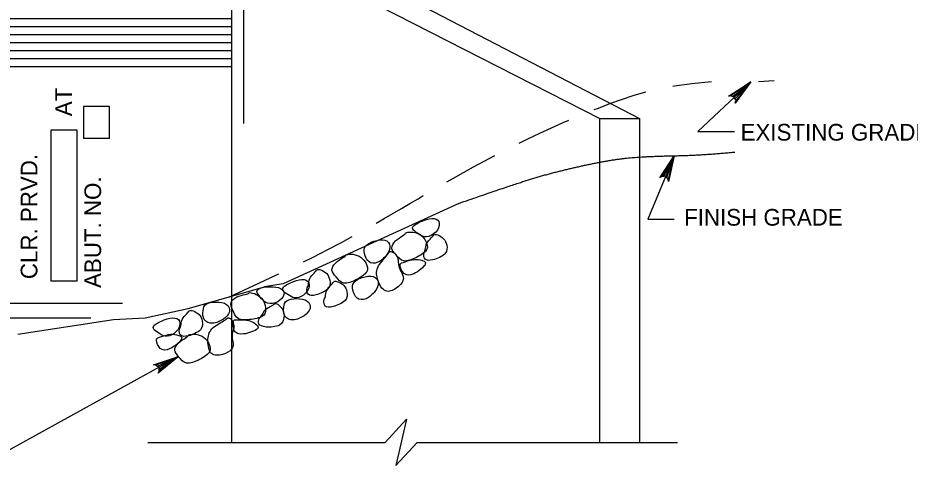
# Model space of a CAD drawing. Extents: x 638263 to 640391, y 293683 to 298655.
# Drawn here: x 638728.4 to 638888.9, y 297385.6 to 297468.7 of the extents above; entities that cross this region are included whole.
import ezdxf

# ---------------------------------------------------------------- set-up
doc = ezdxf.new("R2010")
doc.units = 0
for name, color, linetype in [('3', 7, 'Continuous'), ('4', 7, 'Continuous'), ('5', 7, 'Continuous'), ('8', 7, 'Continuous')]:
    doc.layers.add(name, color=color, linetype=linetype)

msp = doc.modelspace()

# ---------------------------------------------------------------- linework, layer by layer
at = {"layer": '3'}
for p, q in [((638766.86, 297484.49), (638833.06, 297450.61)), ((638775.07, 297484.49), (638840.19, 297450.61)), ((638766.86, 297480.17), (638766.86, 297418.67)), ((638574.49, 297459.98), (638766.86, 297459.98)), ((638860.22, 297457.21), (638850.73, 297448.28)), ((638833.06, 297450.61), (638840.19, 297450.61)), ((638833.06, 297442.76), (638833.06, 297450.61)), ((638840.19, 297450.61), (638840.19, 297443.67)), ((638850.73, 297448.28), (638857.33, 297448.28)), ((638833.06, 297392.39), (638833.06, 297442.76)), ((638840.19, 297443.67), (638840.19, 297392.39)), ((638846.45, 297443.93), (638841.69, 297432.53)), ((638807.71, 297435.38), (638776.12, 297420.89)), ((638841.69, 297432.53), (638846.46, 297432.53)), ((638776.12, 297420.89), (638772.8, 297420.39)), ((638766.86, 297418.67), (638766.86, 297392.39)), ((638580.85, 297414.78), (638741.58, 297414.78)), ((638794.47, 297392.39), (638798.31, 297396.56)), ((638798.31, 297396.56), (638796.38, 297388.22)), ((638751.78, 297392.39), (638794.47, 297392.39)), ((638796.38, 297388.22), (638800.23, 297392.39)), ((638800.23, 297392.39), (638847.06, 297392.39))]:
    msp.add_line(p, q, dxfattribs=at)
msp.add_lwpolyline([(638844.86, 297441.39), (638845.77, 297441.01), (638846.45, 297443.93)], close=True, dxfattribs=at)
for points, degree in [([(638807.71, 297435.38), (638815.49, 297438.06), (638822.64, 297440.39), (638829.78, 297442.14), (638836.53, 297443.45), (638842.88, 297443.88), (638851.42, 297444.03), (638857.38, 297444.61)], 2), ([(638799.58, 297430.54), (638799.82, 297430.29), (638800.68, 297429.73), (638801.79, 297429.09), (638803.77, 297430.03), (638804.53, 297431.96), (638803.44, 297432.86), (638801.42, 297432.42), (638799.24, 297431.28), (638799.34, 297430.8), (638799.58, 297430.54)], 3), ([(638798.16, 297429.99), (638798.11, 297429.9), (638797.78, 297429.62), (638796.19, 297428.7), (638795.39, 297427.27), (638796.4, 297426.22), (638797.6, 297424.59), (638800.18, 297425.59), (638802.4, 297427), (638801.85, 297428.6), (638801.06, 297429.73), (638799.46, 297430.33), (638798.11, 297430.13), (638798.22, 297430.07), (638798.16, 297429.99)], 3), ([(638790.94, 297427.65), (638790.66, 297427.28), (638790.69, 297426.44), (638791.32, 297424.61), (638793.16, 297424.48), (638794.91, 297426.1), (638795.61, 297427.73), (638794.64, 297429.07), (638792.37, 297428.67), (638791.22, 297428.02), (638790.94, 297427.65)], 3), ([(638801.7, 297427.05), (638801.63, 297426.74), (638801.33, 297426.38), (638801.48, 297425.16), (638802.82, 297424.99), (638805.72, 297426.24), (638805.62, 297427.99), (638805.11, 297429.09), (638803.85, 297429.8), (638803.2, 297429.83), (638802.9, 297429.22), (638801.73, 297428.18), (638801.76, 297427.35), (638801.7, 297427.05)], 3), ([(638795.26, 297426.68), (638795.12, 297426.59), (638795.01, 297426.13), (638792.74, 297423.82), (638792.99, 297421.61), (638794.39, 297419.03), (638796.59, 297420.04), (638798, 297421.54), (638797.53, 297422.92), (638796.78, 297423.93), (638796.93, 297425.77), (638795.84, 297426.67), (638795.4, 297426.77), (638795.26, 297426.68)], 3), ([(638787.39, 297426.01), (638787.33, 297425.92), (638787, 297425.64), (638785.41, 297424.72), (638784.62, 297423.29), (638785.62, 297422.24), (638786.83, 297420.61), (638789.4, 297421.61), (638791.62, 297423.02), (638791.08, 297424.62), (638790.29, 297425.74), (638788.68, 297426.35), (638787.34, 297426.14), (638787.44, 297426.09), (638787.39, 297426.01)], 3), ([(638797.71, 297424.76), (638797.29, 297424.62), (638796.98, 297424.51), (638797.69, 297422.46), (638799.41, 297422.28), (638802.53, 297424.75), (638800.69, 297425.28), (638799.5, 297425.38), (638798.13, 297424.91), (638797.71, 297424.76)], 3), ([(638780.67, 297420.75), (638780.61, 297420.45), (638780.3, 297420.09), (638780.46, 297418.86), (638781.8, 297418.69), (638784.69, 297419.94), (638784.6, 297421.7), (638784.09, 297422.8), (638782.83, 297423.51), (638782.17, 297423.54), (638781.87, 297422.92), (638780.7, 297421.89), (638780.74, 297421.05), (638780.67, 297420.75)], 3), ([(638788.83, 297421.1), (638788.56, 297420.73), (638788.59, 297419.89), (638789.22, 297418.06), (638791.06, 297417.93), (638792.81, 297419.55), (638793.51, 297421.18), (638792.54, 297422.52), (638790.27, 297422.12), (638789.11, 297421.47), (638788.83, 297421.1)], 3), ([(638771.49, 297419.31), (638771.63, 297418.99), (638772.27, 297418.18), (638773.11, 297417.22), (638775.29, 297417.46), (638776.63, 297419.04), (638775.9, 297420.24), (638773.85, 297420.49), (638771.41, 297420.12), (638771.35, 297419.63), (638771.49, 297419.31)], 3), ([(638776.19, 297419.56), (638776.43, 297419.31), (638777.29, 297418.75), (638778.4, 297418.11), (638780.38, 297419.05), (638781.14, 297420.98), (638780.05, 297421.88), (638778.03, 297421.44), (638775.85, 297420.3), (638775.95, 297419.82), (638776.19, 297419.56)], 3), ([(638783.74, 297418.63), (638783.67, 297418.33), (638783.37, 297417.97), (638783.52, 297416.74), (638784.87, 297416.57), (638787.76, 297417.82), (638787.67, 297419.58), (638787.15, 297420.68), (638785.89, 297421.39), (638785.24, 297421.42), (638784.94, 297420.81), (638783.77, 297419.77), (638783.81, 297418.93), (638783.74, 297418.63)], 3), ([(638769.97, 297419.24), (638769.89, 297419.18), (638769.49, 297419.02), (638767.69, 297418.67), (638766.47, 297417.57), (638767.08, 297416.25), (638767.69, 297414.32), (638770.45, 297414.43), (638773.01, 297415.04), (638773.01, 297416.73), (638772.63, 297418.05), (638771.31, 297419.15), (638769.97, 297419.39), (638770.05, 297419.3), (638769.97, 297419.24)], 3), ([(638762.29, 297417.26), (638761.91, 297417), (638761.67, 297416.19), (638761.67, 297414.26), (638763.37, 297413.54), (638765.55, 297414.5), (638766.74, 297415.82), (638766.26, 297417.4), (638763.98, 297417.75), (638762.67, 297417.52), (638762.29, 297417.26)], 3), ([(638772.36, 297415.31), (638772.2, 297415.05), (638771.79, 297414.8), (638771.54, 297413.59), (638772.76, 297413), (638775.9, 297413.24), (638776.38, 297414.93), (638776.25, 297416.14), (638775.29, 297417.22), (638774.68, 297417.46), (638774.2, 297416.97), (638772.76, 297416.38), (638772.52, 297415.57), (638772.36, 297415.31)], 3), ([(638776.8, 297417.87), (638776.42, 297417.61), (638776.18, 297416.8), (638776.18, 297414.87), (638777.88, 297414.14), (638780.06, 297415.11), (638781.25, 297416.43), (638780.77, 297418.01), (638778.49, 297418.36), (638777.19, 297418.13), (638776.8, 297417.87)], 3), ([(638757.74, 297413.38), (638757.67, 297413.08), (638757.37, 297412.72), (638757.52, 297411.49), (638758.86, 297411.32), (638761.76, 297412.57), (638761.66, 297414.33), (638761.15, 297415.43), (638759.89, 297416.14), (638759.24, 297416.17), (638758.94, 297415.55), (638757.77, 297414.52), (638757.8, 297413.68), (638757.74, 297413.38)], 3), ([(638752.94, 297412.65), (638753.18, 297412.4), (638754.04, 297411.84), (638755.15, 297411.2), (638757.13, 297412.14), (638757.89, 297414.07), (638756.8, 297414.97), (638754.78, 297414.53), (638752.6, 297413.39), (638752.7, 297412.91), (638752.94, 297412.65)], 3), ([(638766.24, 297414.81), (638766.08, 297414.77), (638765.82, 297414.37), (638762.93, 297412.93), (638762.45, 297410.75), (638762.93, 297407.85), (638765.34, 297408.09), (638767.17, 297409.06), (638767.17, 297410.51), (638766.79, 297411.72), (638767.52, 297413.41), (638766.79, 297414.62), (638766.4, 297414.85), (638766.24, 297414.81)], 3), ([(638767.84, 297414.45), (638767.4, 297414.45), (638767.08, 297414.45), (638767.08, 297412.27), (638768.65, 297411.55), (638772.4, 297412.87), (638770.83, 297413.97), (638769.74, 297414.45), (638768.29, 297414.45), (638767.84, 297414.45)], 3), ([(638753.88, 297411.29), (638753.46, 297411.14), (638753.16, 297411.04), (638753.86, 297408.98), (638755.58, 297408.81), (638758.7, 297411.28), (638756.86, 297411.8), (638755.67, 297411.91), (638754.3, 297411.43), (638753.88, 297411.29)], 3), ([(638759.11, 297411.61), (638759.06, 297411.53), (638758.72, 297411.24), (638757.14, 297410.32), (638756.34, 297408.89), (638757.35, 297407.84), (638758.55, 297406.21), (638761.13, 297407.22), (638763.35, 297408.63), (638762.8, 297410.23), (638762.01, 297411.35), (638760.41, 297411.96), (638759.06, 297411.75), (638759.17, 297411.7), (638759.11, 297411.61)], 3)]:
    msp.add_open_spline(points, degree=degree, dxfattribs=at)
at = {"layer": '4'}
for p, q in [((638769.01, 297515.36), (638769.01, 297449.75)), ((638740.23, 297452.77), (638740.23, 297447.02)), ((638744.93, 297452.77), (638740.23, 297452.77)), ((638744.93, 297447.02), (638744.93, 297452.77)), ((638734.38, 297448.51), (638734.38, 297421.36)), ((638739.09, 297448.51), (638734.38, 297448.51)), ((638739.09, 297421.36), (638739.09, 297448.51)), ((638744.93, 297447.02), (638740.23, 297447.02)), ((638739.09, 297421.36), (638734.38, 297421.36)), ((638716.39, 297417.42), (638747.22, 297417.42)), ((638757.31, 297407.83), (638717.09, 297385.6))]:
    msp.add_line(p, q, dxfattribs=at)
for points in [[(638860.22, 297457.21), (638857.42, 297453.38), (638857.52, 297453.8), (638857.44, 297454.16), (638857.26, 297454.42), (638857.01, 297454.61), (638856.66, 297454.71), (638856.23, 297454.65), (638860.22, 297457.21), (638856.66, 297454.71), (638857.01, 297454.61), (638860.22, 297457.21), (638857.26, 297454.42), (638857.44, 297454.16), (638860.22, 297457.21), (638857.52, 297453.8)], [(638846.45, 297443.93), (638845.46, 297439.29), (638845.37, 297439.72), (638845.16, 297440.01), (638844.89, 297440.18), (638844.58, 297440.25), (638844.22, 297440.2), (638843.85, 297439.96), (638846.45, 297443.93), (638844.22, 297440.2), (638844.58, 297440.25), (638846.45, 297443.93), (638844.89, 297440.18), (638845.16, 297440.01), (638846.45, 297443.93), (638845.37, 297439.72)], [(638728.43, 297411.86), (638745.65, 297414.47), (638751.33, 297414.81), (638759.06, 297416.48), (638772.8, 297420.39)], [(638757.31, 297407.83), (638753.65, 297404.81), (638753.85, 297405.2), (638753.86, 297405.57), (638753.76, 297405.87), (638753.56, 297406.11), (638753.24, 297406.3), (638752.81, 297406.34), (638757.31, 297407.83), (638753.24, 297406.3), (638753.56, 297406.11), (638757.31, 297407.83), (638753.76, 297405.87), (638753.86, 297405.57), (638757.31, 297407.83), (638753.85, 297405.2)]]:
    msp.add_lwpolyline(points, dxfattribs=at)
at = {"layer": '5'}
for p, q in [((638574.49, 297468.63), (638766.86, 297468.63)), ((638574.49, 297467.19), (638766.86, 297467.19)), ((638574.49, 297465.75), (638766.86, 297465.75)), ((638574.49, 297464.31), (638766.86, 297464.31)), ((638574.49, 297462.87), (638766.86, 297462.87)), ((638574.49, 297461.42), (638766.86, 297461.42))]:
    msp.add_line(p, q, dxfattribs=at)
at = {"layer": '8'}
for p, q in [((638849.62, 297456.94), (638853.14, 297457.3)), ((638861.6, 297457.3), (638864.43, 297457.48)), ((638846.19, 297456.45), (638846.52, 297456.51)), ((638846.52, 297456.51), (638849.62, 297456.94)), ((638834.89, 297453.32), (638836.96, 297454.07)), ((638836.96, 297454.07), (638839.08, 297454.77)), ((638839.08, 297454.77), (638841.33, 297455.41)), ((638841.33, 297455.41), (638841.37, 297455.42)), ((638832.07, 297452.23), (638832.82, 297452.52)), ((638832.82, 297452.52), (638834.89, 297453.32)), ((638824.42, 297448.98), (638826.52, 297449.92)), ((638826.52, 297449.92), (638827.52, 297450.35)), ((638820.25, 297447.04), (638822.32, 297448.02)), ((638822.32, 297448.02), (638824.42, 297448.98)), ((638818.58, 297446.23), (638820.25, 297447.04)), ((638810.38, 297441.95), (638812.27, 297442.97)), ((638812.27, 297442.97), (638814.2, 297444)), ((638808.54, 297440.93), (638810.38, 297441.95)), ((638805.58, 297439.25), (638806.77, 297439.93)), ((638806.77, 297439.93), (638808.54, 297440.93)), ((638800.39, 297436.21), (638801.33, 297436.77)), ((638797.42, 297434.45), (638798.91, 297435.33)), ((638798.91, 297435.33), (638800.39, 297436.21)), ((638794.29, 297432.63), (638795.89, 297433.55)), ((638795.89, 297433.55), (638797.42, 297434.45)), ((638792.84, 297431.79), (638794.29, 297432.63)), ((638784.15, 297427.06), (638786.6, 297428.35)), ((638786.6, 297428.35), (638788.54, 297429.39)), ((638781.41, 297425.66), (638784.15, 297427.06)), ((638779.8, 297424.87), (638781.41, 297425.66)), ((638770.88, 297420.59), (638774.82, 297422.44)), ((638774.82, 297422.44), (638775.38, 297422.71)), ((638766.46, 297418.55), (638770.88, 297420.59))]:
    msp.add_line(p, q, dxfattribs=at)

# ---------------------------------------------------------------- texts
at = {"layer": '4'}
for s, p in [('AT', (638738.14, 297451.05)), ('CLR. PRVD.', (638731.94, 297421.75)), ('ABUT. NO. ', (638743.4, 297420.16))]:
    msp.add_text(s, height=3, rotation=90, dxfattribs=at).set_placement(p)
for s, p in [('EXISTING GRADE', (638858.4, 297446.66)), ('FINISH GRADE', (638848.24, 297431.37))]:
    msp.add_text(s, height=3, dxfattribs=at).set_placement(p)

doc.saveas('drawing.dxf')
